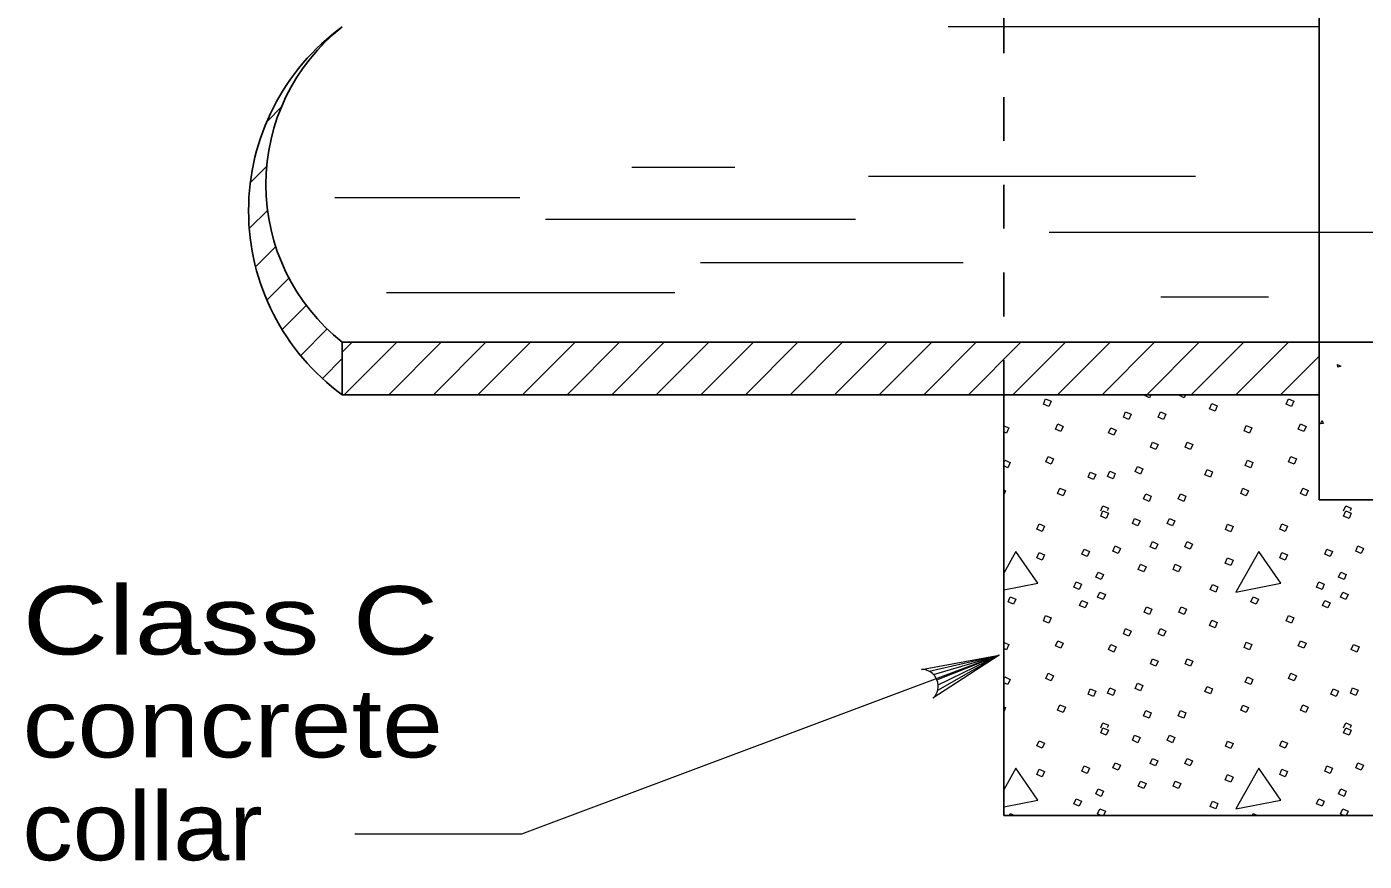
# Model space of a CAD drawing. Extents: x 1083.1 to 1117.1, y 697.4 to 741.4.
# Drawn here: x 1108.974 to 1112.027, y 728.567 to 730.47 of the extents above; entities that cross this region are included whole.
import ezdxf

# ---------------------------------------------------------------- set-up
doc = ezdxf.new("R2010")
doc.units = 0
doc.header["$LTSCALE"] = 0.062
doc.linetypes.add('SHORT_DASHED', pattern=[2.7, 1.5, -1.2])
doc.layers.add('1', color=7, linetype='Continuous', lineweight=13)

msp = doc.modelspace()

# ---------------------------------------------------------------- linework, layer by layer
at = {"layer": '1', "lineweight": 25}
for p, q in [((1111.92392, 731.5495), (1111.92392, 729.63058)), ((1109.69433, 729.7505), (1109.69433, 729.63058)), ((1114.15358, 729.7505), (1109.69433, 729.7505)), ((1109.69433, 729.63058), (1111.20425, 729.63058)), ((1111.20425, 728.67117), (1111.20425, 729.63058)), ((1112.64358, 728.67117), (1111.20425, 728.67117))]:
    msp.add_line(p, q, dxfattribs=at)
at = {"layer": '1', "linetype": 'SHORT_DASHED', "lineweight": 25}
msp.add_line((1111.20425, 731.30958), (1111.20425, 729.63058), dxfattribs=at)
at = {"layer": '1'}
for p, q in [((1111.92392, 730.47008), (1111.07717, 730.47008)), ((1109.5225, 730.25425), (1109.5565, 730.28808)), ((1109.48467, 730.1145), (1109.52217, 730.15208)), ((1110.5905, 730.14908), (1110.35483, 730.14908)), ((1110.89517, 730.12942), (1111.64167, 730.12942)), ((1110.09933, 730.08025), (1109.67692, 730.08025)), ((1109.48233, 730.01042), (1109.524, 730.052)), ((1110.15833, 730.031), (1110.86567, 730.031)), ((1111.30775, 730.0015), (1112.41783, 730.0015)), ((1109.49692, 729.92325), (1109.54258, 729.96883)), ((1110.51192, 729.93267), (1111.11133, 729.93267)), ((1109.52233, 729.84683), (1109.57292, 729.89742)), ((1109.79483, 729.86383), (1110.45308, 729.86383)), ((1111.56317, 729.85392), (1111.80875, 729.85392)), ((1109.55708, 729.77992), (1109.61225, 729.83508)), ((1109.59958, 729.7205), (1109.66008, 729.78108)), ((1109.69433, 729.72808), (1109.71675, 729.7505)), ((1109.6985, 729.63058), (1109.81842, 729.7505)), ((1109.80033, 729.63058), (1109.92025, 729.7505)), ((1109.90208, 729.63058), (1110.022, 729.7505)), ((1110.00383, 729.63058), (1110.12383, 729.7505)), ((1110.10567, 729.63058), (1110.22567, 729.7505)), ((1110.20742, 729.63058), (1110.32733, 729.7505)), ((1110.30925, 729.63058), (1110.42917, 729.7505)), ((1110.411, 729.63058), (1110.53092, 729.7505)), ((1110.51283, 729.63058), (1110.63275, 729.7505)), ((1110.6145, 729.63058), (1110.73442, 729.7505)), ((1110.71633, 729.63058), (1110.83625, 729.7505)), ((1110.81808, 729.63058), (1110.938, 729.7505)), ((1110.91992, 729.63058), (1111.03983, 729.7505)), ((1111.02158, 729.63058), (1111.1415, 729.7505)), ((1111.12342, 729.63058), (1111.24333, 729.7505)), ((1111.22517, 729.63058), (1111.34508, 729.7505)), ((1111.327, 729.63058), (1111.44692, 729.7505)), ((1111.42867, 729.63058), (1111.54858, 729.7505)), ((1111.5305, 729.63058), (1111.6505, 729.7505)), ((1111.63225, 729.63058), (1111.75217, 729.7505)), ((1111.73408, 729.63058), (1111.854, 729.7505)), ((1109.64883, 729.668), (1109.69433, 729.7135)), ((1111.83592, 729.63058), (1111.92392, 729.71858)), ((1111.20425, 729.4765), (1111.20642, 729.48142)), ((1111.42575, 729.36567), (1111.43075, 729.37708)), ((1111.98008, 729.36567), (1111.98508, 729.37708)), ((1111.23208, 729.27325), (1111.20425, 729.224)), ((1111.03425, 728.99983), (1111.19408, 729.03658)), ((1111.04383, 728.99242), (1111.19408, 729.03658)), ((1111.05175, 728.98008), (1111.19408, 729.03658)), ((1111.05342, 728.95667), (1111.19408, 729.03658)), ((1111.05442, 728.969), (1111.19408, 729.03658)), ((1111.20425, 728.98208), (1111.20642, 728.98692)), ((1111.42575, 728.87125), (1111.43075, 728.88267)), ((1111.98008, 728.87125), (1111.98508, 728.88267)), ((1111.23208, 728.77875), (1111.20425, 728.7295)), ((1111.21708, 728.67117), (1111.21908, 728.67558)), ((1111.21908, 728.67558), (1111.22933, 728.67117)), ((1111.77142, 728.67117), (1111.77333, 728.67558)), ((1111.77333, 728.67558), (1111.78367, 728.67117))]:
    msp.add_line(p, q, dxfattribs=at)
for points in [[(1111.97367, 729.69558), (1111.967, 729.69333), (1111.966, 729.69958)], [(1111.29975, 729.62142), (1111.31225, 729.616), (1111.30708, 729.60417), (1111.29458, 729.60958)], [(1111.67925, 729.61075), (1111.69175, 729.60533), (1111.68658, 729.5935), (1111.67408, 729.59892)], [(1111.85408, 729.62142), (1111.86658, 729.616), (1111.86142, 729.60417), (1111.84892, 729.60958)], [(1111.4825, 729.59167), (1111.495, 729.58625), (1111.48983, 729.57442), (1111.47733, 729.57983)], [(1111.56175, 729.59167), (1111.57425, 729.58625), (1111.56908, 729.57442), (1111.55658, 729.57983)], [(1111.32742, 729.564), (1111.33992, 729.55858), (1111.33475, 729.54675), (1111.32225, 729.55217)], [(1111.4485, 729.5555), (1111.461, 729.55008), (1111.45583, 729.53825), (1111.44333, 729.54367)], [(1111.75783, 729.5605), (1111.77033, 729.55508), (1111.76517, 729.54325), (1111.75267, 729.54867)], [(1111.88175, 729.564), (1111.89425, 729.55858), (1111.88908, 729.54675), (1111.87658, 729.55217)], [(1111.93125, 729.57183), (1111.93367, 729.56508), (1111.92725, 729.56425)], [(1111.54408, 729.52292), (1111.55658, 729.5175), (1111.55142, 729.50567), (1111.53892, 729.51108)], [(1111.62325, 729.52292), (1111.63575, 729.5175), (1111.63058, 729.50567), (1111.61808, 729.51108)], [(1111.30542, 729.48975), (1111.31792, 729.48433), (1111.31275, 729.4725), (1111.30025, 729.47792)], [(1111.85975, 729.48975), (1111.87225, 729.48433), (1111.86708, 729.4725), (1111.85458, 729.47792)], [(1111.40183, 729.45433), (1111.41433, 729.44892), (1111.40917, 729.43708), (1111.39667, 729.4425)], [(1111.44633, 729.45642), (1111.45883, 729.451), (1111.45367, 729.43917), (1111.44117, 729.44458)], [(1111.50942, 729.46708), (1111.52192, 729.46167), (1111.51675, 729.44983), (1111.50425, 729.45525)], [(1111.66858, 729.46), (1111.68108, 729.45458), (1111.67592, 729.44275), (1111.66342, 729.44817)], [(1111.76075, 729.48142), (1111.77317, 729.476), (1111.76808, 729.46417), (1111.75558, 729.46958)], [(1111.33233, 729.4175), (1111.34483, 729.41208), (1111.33967, 729.40025), (1111.32717, 729.40567)], [(1111.5285, 729.40475), (1111.541, 729.39933), (1111.53583, 729.3875), (1111.52333, 729.39292)], [(1111.60767, 729.40475), (1111.62017, 729.39933), (1111.615, 729.3875), (1111.6025, 729.39292)], [(1111.75033, 729.41725), (1111.76283, 729.41183), (1111.75767, 729.4), (1111.74517, 729.40542)], [(1111.88667, 729.4175), (1111.89917, 729.41208), (1111.894, 729.40025), (1111.8815, 729.40567)], [(1111.43075, 729.36567), (1111.44325, 729.36025), (1111.43808, 729.3485), (1111.42558, 729.35392)], [(1111.98508, 729.36567), (1111.99758, 729.36025), (1111.99242, 729.3485), (1111.97992, 729.35392)], [(1111.28492, 729.336), (1111.29742, 729.33058), (1111.29225, 729.31875), (1111.27975, 729.32417)], [(1111.503, 729.34875), (1111.5155, 729.34333), (1111.51033, 729.3315), (1111.49783, 729.33692)], [(1111.58225, 729.34875), (1111.59467, 729.34333), (1111.58958, 729.3315), (1111.57708, 729.33692)], [(1111.71533, 729.33533), (1111.72783, 729.32992), (1111.72267, 729.31808), (1111.71017, 729.3235)], [(1111.83925, 729.336), (1111.85175, 729.33058), (1111.84658, 729.31875), (1111.83408, 729.32417)], [(1111.28492, 729.27083), (1111.29742, 729.26542), (1111.29225, 729.25358), (1111.27975, 729.259)], [(1111.38767, 729.27867), (1111.40017, 729.27325), (1111.395, 729.26142), (1111.3825, 729.26683)], [(1111.45842, 729.28575), (1111.47092, 729.28033), (1111.46575, 729.2685), (1111.45325, 729.27392)], [(1111.54342, 729.29567), (1111.55592, 729.29025), (1111.55075, 729.27842), (1111.53825, 729.28383)], [(1111.62258, 729.29567), (1111.63508, 729.29025), (1111.62992, 729.27842), (1111.61742, 729.28383)], [(1111.78633, 729.27325), (1111.73417, 729.18067), (1111.83642, 729.20067)], [(1111.83925, 729.27083), (1111.85175, 729.26542), (1111.84658, 729.25358), (1111.83408, 729.259)], [(1111.942, 729.27867), (1111.95442, 729.27325), (1111.94925, 729.26142), (1111.93683, 729.26683)], [(1112.01275, 729.28575), (1112.02525, 729.28033), (1112.02008, 729.2685), (1112.00758, 729.27392)], [(1111.5165, 729.24392), (1111.529, 729.2385), (1111.52383, 729.22667), (1111.51133, 729.23208)], [(1111.59567, 729.24392), (1111.60817, 729.2385), (1111.603, 729.22667), (1111.59058, 729.23208)], [(1111.71508, 729.25858), (1111.72758, 729.25317), (1111.72242, 729.24133), (1111.70992, 729.24675)], [(1111.41942, 729.22625), (1111.43192, 729.22083), (1111.42675, 729.20908), (1111.41433, 729.21442)], [(1111.97375, 729.22625), (1111.98625, 729.22083), (1111.98108, 729.20908), (1111.96858, 729.21442)], [(1111.36917, 729.20367), (1111.38167, 729.19825), (1111.3765, 729.18642), (1111.364, 729.19183)], [(1111.42367, 729.18075), (1111.43617, 729.17533), (1111.431, 729.1635), (1111.41858, 729.16892)], [(1111.68067, 729.198), (1111.69317, 729.19258), (1111.688, 729.18075), (1111.6755, 729.18617)], [(1111.9235, 729.20367), (1111.936, 729.19825), (1111.93083, 729.18642), (1111.91833, 729.19183)], [(1111.978, 729.18075), (1111.9905, 729.17533), (1111.98533, 729.1635), (1111.97283, 729.16892)], [(1111.21908, 729.17008), (1111.23158, 729.16467), (1111.22642, 729.15283), (1111.21392, 729.15825)], [(1111.38267, 729.16158), (1111.39517, 729.15617), (1111.39, 729.14433), (1111.3775, 729.14975)], [(1111.52992, 729.14675), (1111.54242, 729.14133), (1111.53725, 729.1295), (1111.52475, 729.13492)], [(1111.60908, 729.14675), (1111.62158, 729.14133), (1111.61642, 729.1295), (1111.60392, 729.13492)], [(1111.77333, 729.17008), (1111.78583, 729.16467), (1111.78067, 729.15283), (1111.76817, 729.15825)], [(1111.937, 729.16158), (1111.94942, 729.15617), (1111.94433, 729.14433), (1111.93183, 729.14975)], [(1111.29975, 729.12692), (1111.31225, 729.1215), (1111.30708, 729.10967), (1111.29458, 729.11508)], [(1111.67925, 729.11625), (1111.69175, 729.11083), (1111.68658, 729.099), (1111.67408, 729.10442)], [(1111.85408, 729.12692), (1111.86658, 729.1215), (1111.86142, 729.10967), (1111.84892, 729.11508)], [(1111.4825, 729.09717), (1111.495, 729.09175), (1111.48983, 729.07992), (1111.47733, 729.08533)], [(1111.56175, 729.09717), (1111.57425, 729.09175), (1111.56908, 729.07992), (1111.55658, 729.08533)], [(1111.32742, 729.0695), (1111.33992, 729.06408), (1111.33475, 729.05233), (1111.32225, 729.05775)], [(1111.4485, 729.06108), (1111.461, 729.05567), (1111.45583, 729.04383), (1111.44333, 729.04925)], [(1111.75783, 729.066), (1111.77033, 729.06067), (1111.76517, 729.04883), (1111.75267, 729.05425)], [(1111.88175, 729.0695), (1111.89425, 729.06408), (1111.88908, 729.05233), (1111.87658, 729.05775)], [(1112.00283, 729.06108), (1112.01533, 729.05567), (1112.01017, 729.04383), (1111.99767, 729.04925)], [(1111.54408, 729.0285), (1111.55658, 729.02308), (1111.55142, 729.01125), (1111.53892, 729.01667)], [(1111.62325, 729.0285), (1111.63575, 729.02308), (1111.63058, 729.01125), (1111.61808, 729.01667)], [(1111.30542, 728.99525), (1111.31792, 728.98983), (1111.31275, 728.978), (1111.30025, 728.98342)], [(1111.85975, 728.99525), (1111.87225, 728.98983), (1111.86708, 728.978), (1111.85458, 728.98342)], [(1111.50942, 728.97258), (1111.52192, 728.96717), (1111.51675, 728.95533), (1111.50425, 728.96075)], [(1111.66858, 728.9655), (1111.68108, 728.96008), (1111.67592, 728.94825), (1111.66342, 728.95367)], [(1111.76075, 728.98692), (1111.77317, 728.9815), (1111.76808, 728.96967), (1111.75558, 728.97508)], [(1111.40183, 728.95983), (1111.41433, 728.95442), (1111.40917, 728.94258), (1111.39667, 728.948)], [(1111.44633, 728.96192), (1111.45883, 728.9565), (1111.45367, 728.94467), (1111.44117, 728.95008)], [(1111.95608, 728.95983), (1111.96858, 728.95442), (1111.96342, 728.94258), (1111.95092, 728.948)], [(1112.00067, 728.96192), (1112.01317, 728.9565), (1112.008, 728.94467), (1111.9955, 728.95008)], [(1111.33233, 728.923), (1111.34483, 728.91767), (1111.33967, 728.90583), (1111.32717, 728.91125)], [(1111.5285, 728.91033), (1111.541, 728.90492), (1111.53583, 728.89308), (1111.52333, 728.8985)], [(1111.60767, 728.91033), (1111.62017, 728.90492), (1111.615, 728.89308), (1111.6025, 728.8985)], [(1111.75033, 728.92275), (1111.76283, 728.91733), (1111.75767, 728.90558), (1111.74517, 728.911)], [(1111.88667, 728.923), (1111.89917, 728.91767), (1111.894, 728.90583), (1111.8815, 728.91125)], [(1111.43075, 728.87125), (1111.44325, 728.86583), (1111.43808, 728.854), (1111.42558, 728.85942)], [(1111.98508, 728.87125), (1111.99758, 728.86583), (1111.99242, 728.854), (1111.97992, 728.85942)], [(1111.28492, 728.8415), (1111.29742, 728.83608), (1111.29225, 728.82425), (1111.27975, 728.82967)], [(1111.503, 728.85425), (1111.5155, 728.84883), (1111.51033, 728.837), (1111.49783, 728.84242)], [(1111.58225, 728.85425), (1111.59467, 728.84883), (1111.58958, 728.837), (1111.57708, 728.84242)], [(1111.71533, 728.84083), (1111.72783, 728.83542), (1111.72267, 728.82358), (1111.71017, 728.829)], [(1111.83925, 728.8415), (1111.85175, 728.83608), (1111.84658, 728.82425), (1111.83408, 728.82967)], [(1111.38767, 728.78417), (1111.40017, 728.77875), (1111.395, 728.767), (1111.3825, 728.77242)], [(1111.45842, 728.79125), (1111.47092, 728.78583), (1111.46575, 728.77408), (1111.45325, 728.77942)], [(1111.54342, 728.80117), (1111.55592, 728.79575), (1111.55075, 728.78392), (1111.53825, 728.78933)], [(1111.62258, 728.80117), (1111.63508, 728.79575), (1111.62992, 728.78392), (1111.61742, 728.78933)], [(1111.942, 728.78417), (1111.95442, 728.77875), (1111.94925, 728.767), (1111.93683, 728.77242)], [(1112.01275, 728.79125), (1112.02525, 728.78583), (1112.02008, 728.77408), (1112.00758, 728.77942)], [(1111.28492, 728.77642), (1111.29742, 728.771), (1111.29225, 728.75917), (1111.27975, 728.76458)], [(1111.5165, 728.7495), (1111.529, 728.74408), (1111.52383, 728.73225), (1111.51133, 728.73767)], [(1111.59567, 728.7495), (1111.60817, 728.74408), (1111.603, 728.73225), (1111.59058, 728.73767)], [(1111.71508, 728.76417), (1111.72758, 728.75875), (1111.72242, 728.74692), (1111.70992, 728.75233)], [(1111.78633, 728.77875), (1111.73417, 728.68617), (1111.83642, 728.70617)], [(1111.83925, 728.77642), (1111.85175, 728.771), (1111.84658, 728.75917), (1111.83408, 728.76458)], [(1111.41942, 728.73183), (1111.43192, 728.72642), (1111.42675, 728.71458), (1111.41433, 728.72)], [(1111.97375, 728.73183), (1111.98625, 728.72642), (1111.98108, 728.71458), (1111.96858, 728.72)], [(1111.36917, 728.70917), (1111.38167, 728.70375), (1111.3765, 728.69192), (1111.364, 728.69733)], [(1111.68067, 728.7035), (1111.69317, 728.69808), (1111.688, 728.68625), (1111.6755, 728.69167)], [(1111.9235, 728.70917), (1111.936, 728.70375), (1111.93083, 728.69192), (1111.91833, 728.69733)]]:
    msp.add_lwpolyline(points, close=True, dxfattribs=at)
at = {"layer": '1', "lineweight": 25}
for points in [[(1111.20425, 729.63058), (1111.92392, 729.63058), (1111.92392, 729.39075)], [(1112.64358, 728.67117), (1112.64358, 729.39075), (1111.92392, 729.39075)]]:
    msp.add_lwpolyline(points, dxfattribs=at)
at = {"layer": '1'}
for points in [[(1111.54008, 729.63058), (1111.53725, 729.624), (1111.52475, 729.62942), (1111.52525, 729.63058)], [(1111.61933, 729.63058), (1111.61642, 729.624), (1111.60392, 729.62942), (1111.6045, 729.63058)], [(1111.20425, 729.56017), (1111.216, 729.55508), (1111.21083, 729.54325), (1111.20425, 729.54608)], [(1111.20642, 729.48142), (1111.21892, 729.476), (1111.21375, 729.46417), (1111.20425, 729.46825)], [(1111.20425, 729.41367), (1111.2085, 729.41183), (1111.20425, 729.40225)], [(1111.43075, 729.37708), (1111.44325, 729.37167), (1111.44067, 729.36567)], [(1111.98508, 729.37708), (1111.99758, 729.37167), (1111.995, 729.36567)], [(1111.20425, 729.18542), (1111.28208, 729.20067), (1111.23208, 729.27325)], [(1111.20425, 729.06567), (1111.216, 729.06067), (1111.21083, 729.04883), (1111.20425, 729.05167)], [(1111.19408, 729.03658), (1110.10367, 728.62833), (1109.723, 728.62833)], [(1111.0165, 729.00425), (1111.19408, 729.03658), (1111.04267, 728.93842)], [(1111.20642, 728.98692), (1111.21892, 728.9815), (1111.21375, 728.96967), (1111.20425, 728.97375)], [(1111.20425, 728.91917), (1111.2085, 728.91733), (1111.20425, 728.90775)], [(1111.43075, 728.88267), (1111.44325, 728.87725), (1111.44067, 728.87125)], [(1111.98508, 728.88267), (1111.99758, 728.87725), (1111.995, 728.87125)], [(1111.20425, 728.69092), (1111.28208, 728.70617), (1111.23208, 728.77875)], [(1111.42617, 728.67117), (1111.41858, 728.67442), (1111.42367, 728.68625)], [(1111.42367, 728.68625), (1111.43617, 728.68083), (1111.432, 728.67117)], [(1111.9805, 728.67117), (1111.97283, 728.67442), (1111.978, 728.68625)], [(1111.978, 728.68625), (1111.9905, 728.68083), (1111.98625, 728.67117)]]:
    msp.add_lwpolyline(points, dxfattribs=at)
msp.add_arc((1111.01631, 728.96601), 0.0382, 313.72354, 89.54967, dxfattribs=at)
at = {"layer": '1', "lineweight": 25}
for centre, major_axis, start_param, end_param in [((1109.99916, 730.05035), (-0.51882, 0), 5.3404824, 7.2258881), ((1109.978, 730.11031), (-0.45822, 0), 5.380032, 7.1863386)]:
    msp.add_ellipse(centre, major_axis=major_axis, ratio=0.999895, start_param=start_param, end_param=end_param, dxfattribs=at)

# ---------------------------------------------------------------- texts
at = {"layer": '1'}
for s, width, p in [('Class C', 1.3, (1108.96417, 729.03817)), ('concrete', 1.2, (1108.96417, 728.8035)), ('collar', 1.1, (1108.96417, 728.56883))]:
    msp.add_text(s, height=0.156, dxfattribs=dict(at, width=width)).set_placement(p)

doc.saveas('drawing.dxf')
